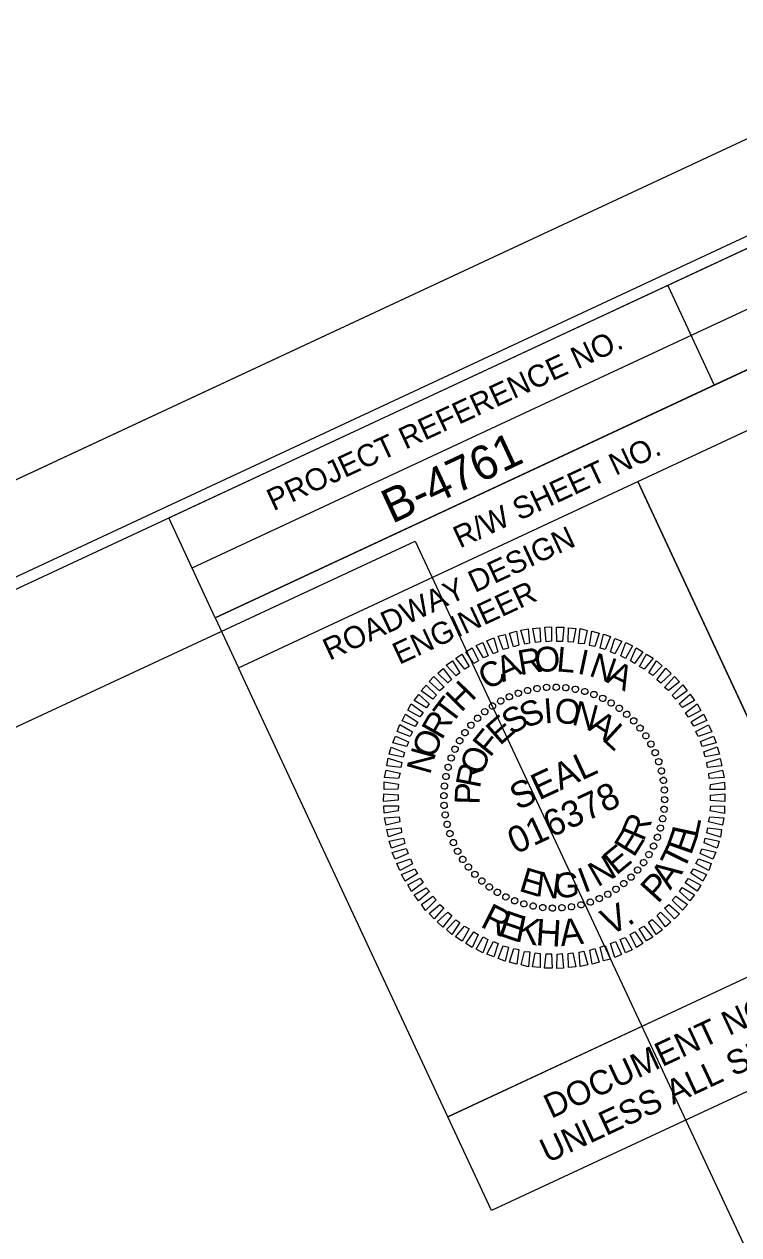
# Model space of a CAD drawing. Extents: x 2321825 to 2323872, y 921700 to 923436.
# Drawn here: x 2323189.3 to 2323351.6, y 923128.5 to 923403.3 of the extents above; entities that cross this region are included whole.
import ezdxf

# ---------------------------------------------------------------- set-up
doc = ezdxf.new("R2010")
doc.units = 0
for name, color, linetype in [('Sheet Cutting Line CELL', 7, 'Continuous'), ('Sheet Data Field CELL', 7, 'Continuous'), ('Sheet Layout Plan Border', 7, 'Continuous'), ('Sheet Plan And Profile CELL', 7, 'Continuous'), ('Sheet Plot Border Inside CELL', 7, 'Continuous'), ('Sheet Plot Border Outside CELL', 7, 'Continuous'), ('Sheet Professional Seal CELL', 7, 'Continuous'), ('Sheet Sticker Exception Certification CELL', 7, 'Continuous')]:
    doc.layers.add(name, color=color, linetype=linetype)

# ---------------------------------------------------------------- blocks, each defined once
blk = doc.blocks.new('STICKER EXCEPTION CERTIFICATION')
at = {"layer": 'Sheet Sticker Exception Certification CELL'}
for p, q in [((0, -0.47), (0, 0)), ((0, 0), (4.0008, 0)), ((4.0008, -0.0003), (4.0008, -0.4703)), ((4.0008, -0.47), (0, -0.47))]:
    blk.add_line(p, q, dxfattribs=at)
for s, p in [('DOCUMENT NOT CONSIDERED FINAL', (0.4214, -0.2069)), ('UNLESS ALL SIGNATURES COMPLETED', (0.32, -0.3829))]:
    blk.add_text(s, height=0.11, dxfattribs=at).set_placement(p)

msp = doc.modelspace()

# ---------------------------------------------------------------- linework, layer by layer
at = {"layer": 'Sheet Cutting Line CELL'}
msp.add_line((2323409.34, 923403.35), (2321883.46, 922692.1), dxfattribs=at)
at = {"layer": 'Sheet Layout Plan Border'}
msp.add_lwpolyline([(2323496.81, 922817.99), (2322321.56, 922264.67), (2322282.6, 922345.71), (2322138.58, 922653.86), (2322100.41, 922737.9), (2323278.09, 923285.95)], close=True, dxfattribs=at)
at = {"layer": 'Sheet Plan And Profile CELL'}
for p, q in [((2323227.42, 923279.88), (2323408.74, 923364.4)), ((2323232.7, 923268.55), (2323414.02, 923353.07)), ((2323335.48, 923344.04), (2323346.04, 923321.38)), ((2323328.66, 923299.49), (2323376.17, 923197.57)), ((2323232.7, 923268.55), (2323237.98, 923257.22))]:
    msp.add_line(p, q, dxfattribs=at)
for points in [[(2323403.44, 923375.77), (2322043.88, 922742.05), (2322487.48, 921790.36), (2323847.04, 922424.08)], [(2323222.12, 923291.26), (2323403.44, 923375.77), (2323414.02, 923353.07), (2323232.7, 923268.55)], [(2323328.66, 923299.49), (2323419.3, 923341.74), (2323466.83, 923239.77), (2323376.19, 923197.52)], [(2323237.98, 923257.22), (2323328.66, 923299.49), (2323376.19, 923197.52), (2323285.51, 923155.25)]]:
    msp.add_lwpolyline(points, close=True, dxfattribs=at)
at = {"layer": 'Sheet Plot Border Inside CELL'}
msp.add_lwpolyline([(2322349.41, 921723.24), (2323859.43, 922427.1), (2323413.71, 923383.32), (2321903.69, 922679.47)], close=True, dxfattribs=at)
at = {"layer": 'Sheet Plot Border Outside CELL'}
msp.add_lwpolyline([(2322346.08, 921699.62), (2323871.95, 922410.87), (2323409.34, 923403.35), (2321883.46, 922692.1)], close=True, dxfattribs=at)
at = {"layer": 'Sheet Professional Seal CELL'}
for p, q in [((2323307.94, 923252.79), (2323307.94, 923252.79)), ((2323310.14, 923252.82), (2323310.14, 923252.82)), ((2323299.5, 923250.68), (2323299.5, 923250.68)), ((2323301.56, 923251.47), (2323301.56, 923251.47)), ((2323303.65, 923252.06), (2323303.65, 923252.06)), ((2323305.75, 923252.54), (2323305.75, 923252.54)), ((2323312.33, 923252.74), (2323312.33, 923252.74)), ((2323314.49, 923252.37), (2323314.49, 923252.37)), ((2323316.64, 923251.88), (2323316.64, 923251.88)), ((2323318.68, 923251.18), (2323318.68, 923251.18)), ((2323320.74, 923250.32), (2323320.74, 923250.32)), ((2323295.7, 923248.52), (2323295.7, 923248.52)), ((2323297.53, 923249.7), (2323297.53, 923249.7)), ((2323322.61, 923249.26), (2323322.61, 923249.26)), ((2323324.46, 923248.02), (2323324.46, 923248.02)), ((2323292.23, 923245.8), (2323292.23, 923245.8)), ((2323293.88, 923247.23), (2323293.88, 923247.23)), ((2323326.19, 923246.68), (2323326.19, 923246.68)), ((2323327.76, 923245.2), (2323327.76, 923245.2)), ((2323289.41, 923242.5), (2323289.41, 923242.5)), ((2323290.75, 923244.23), (2323290.75, 923244.23)), ((2323329.19, 923243.55), (2323329.19, 923243.55)), ((2323288.17, 923240.65), (2323288.17, 923240.65)), ((2323330.48, 923241.73), (2323330.48, 923241.73)), ((2323331.66, 923239.91), (2323331.66, 923239.91)), ((2323286.25, 923236.72), (2323286.25, 923236.72)), ((2323287.11, 923238.78), (2323287.11, 923238.78)), ((2323332.63, 923237.93), (2323332.63, 923237.93)), ((2323285.55, 923234.69), (2323285.55, 923234.69)), ((2323333.43, 923235.88), (2323333.43, 923235.88)), ((2323334.02, 923233.78), (2323334.02, 923233.78)), ((2323285.06, 923232.53), (2323285.06, 923232.53)), ((2323334.5, 923231.69), (2323334.5, 923231.69)), ((2323284.61, 923228.18), (2323284.61, 923228.18)), ((2323284.69, 923230.37), (2323284.69, 923230.37)), ((2323334.75, 923229.49), (2323334.75, 923229.49)), ((2323284.64, 923225.99), (2323284.64, 923225.99)), ((2323309.69, 923227.74), (2323309.69, 923227.74)), ((2323334.78, 923227.29), (2323334.78, 923227.29)), ((2323284.89, 923223.79), (2323284.89, 923223.79)), ((2323334.33, 923222.94), (2323334.33, 923222.94)), ((2323334.7, 923225.1), (2323334.7, 923225.1)), ((2323285.37, 923221.69), (2323285.37, 923221.69)), ((2323333.84, 923220.79), (2323333.84, 923220.79)), ((2323285.96, 923219.6), (2323285.96, 923219.6)), ((2323286.75, 923217.54), (2323286.75, 923217.54)), ((2323333.14, 923218.75), (2323333.14, 923218.75)), ((2323287.73, 923215.57), (2323287.73, 923215.57)), ((2323331.22, 923214.82), (2323331.22, 923214.82)), ((2323332.27, 923216.69), (2323332.27, 923216.69)), ((2323288.91, 923213.74), (2323288.91, 923213.74)), ((2323290.2, 923211.92), (2323290.2, 923211.92)), ((2323329.98, 923212.97), (2323329.98, 923212.97)), ((2323291.63, 923210.27), (2323291.63, 923210.27)), ((2323327.16, 923209.67), (2323327.16, 923209.67)), ((2323328.64, 923211.24), (2323328.64, 923211.24)), ((2323293.2, 923208.8), (2323293.2, 923208.8)), ((2323294.93, 923207.45), (2323294.93, 923207.45)), ((2323296.78, 923206.21), (2323296.78, 923206.21)), ((2323323.69, 923206.95), (2323323.69, 923206.95)), ((2323325.51, 923208.24), (2323325.51, 923208.24)), ((2323298.65, 923205.16), (2323298.65, 923205.16)), ((2323300.71, 923204.29), (2323300.71, 923204.29)), ((2323302.75, 923203.59), (2323302.75, 923203.59)), ((2323315.74, 923203.41), (2323315.74, 923203.41)), ((2323317.83, 923204), (2323317.83, 923204)), ((2323319.89, 923204.8), (2323319.89, 923204.8)), ((2323321.86, 923205.77), (2323321.86, 923205.77)), ((2323304.9, 923203.11), (2323304.9, 923203.11)), ((2323307.06, 923202.73), (2323307.06, 923202.73)), ((2323309.25, 923202.65), (2323309.25, 923202.65)), ((2323311.44, 923202.68), (2323311.44, 923202.68)), ((2323313.64, 923202.93), (2323313.64, 923202.93))]:
    msp.add_line(p, q, dxfattribs=at)
for points in [[(2323295.78, 923260.42), (2323294.41, 923263.37), (2323295.93, 923264.02), (2323296.89, 923260.88)], [(2323298.11, 923261.34), (2323296.92, 923264.37), (2323298.54, 923264.79), (2323299.29, 923261.67)], [(2323300.46, 923261.99), (2323299.51, 923265.08), (2323301.11, 923265.55), (2323301.61, 923262.36)], [(2323303, 923262.57), (2323302.08, 923265.73), (2323303.79, 923266.08), (2323304.06, 923262.79)], [(2323305.45, 923262.99), (2323304.82, 923266.12), (2323306.44, 923266.32), (2323306.55, 923263.12)], [(2323307.87, 923263.13), (2323307.58, 923266.47), (2323309.1, 923266.52), (2323309.06, 923263.3)], [(2323310.31, 923263.22), (2323310.2, 923266.42), (2323311.9, 923266.44), (2323311.54, 923263.19)], [(2323312.88, 923263.15), (2323312.9, 923266.3), (2323314.62, 923266.17), (2323314, 923263.01)], [(2323315.22, 923262.75), (2323315.58, 923266.12), (2323317.2, 923265.71), (2323316.47, 923262.67)], [(2323317.71, 923262.26), (2323318.23, 923265.53), (2323319.87, 923265.08), (2323318.87, 923262.02)], [(2323320.09, 923261.65), (2323320.85, 923264.88), (2323322.44, 923264.29), (2323321.27, 923261.37)], [(2323322.46, 923260.83), (2323323.42, 923263.87), (2323325.01, 923263.28), (2323323.48, 923260.42)], [(2323291.43, 923258.17), (2323289.58, 923260.84), (2323291.03, 923261.74), (2323292.45, 923258.81)], [(2323293.59, 923259.45), (2323291.99, 923262.29), (2323293.5, 923262.94), (2323294.7, 923259.91)], [(2323324.81, 923259.94), (2323325.94, 923262.95), (2323327.46, 923262.17), (2323325.86, 923259.32)], [(2323326.99, 923258.8), (2323328.32, 923261.74), (2323329.8, 923260.83), (2323327.93, 923258.19)], [(2323287.44, 923255.37), (2323285.15, 923257.78), (2323286.55, 923258.82), (2323288.28, 923256.04)], [(2323289.38, 923256.88), (2323287.3, 923259.44), (2323288.73, 923260.28), (2323290.4, 923257.52)], [(2323329.03, 923257.49), (2323330.63, 923260.33), (2323332.13, 923259.38), (2323330.09, 923256.88)], [(2323331.14, 923256.05), (2323332.94, 923258.82), (2323334.18, 923257.69), (2323332.09, 923255.44)], [(2323285.54, 923253.77), (2323283.23, 923256), (2323284.44, 923257.06), (2323286.34, 923254.53)], [(2323332.96, 923254.52), (2323335, 923257.13), (2323336.26, 923255.95), (2323333.87, 923253.74)], [(2323282.1, 923250.13), (2323279.47, 923251.99), (2323280.58, 923253.28), (2323282.91, 923251)], [(2323283.65, 923252.01), (2323281.25, 923254.09), (2323282.36, 923255.26), (2323284.66, 923252.81)], [(2323334.76, 923252.77), (2323336.98, 923255.24), (2323338.13, 923254.07), (2323335.66, 923252.03)], [(2323336.5, 923250.93), (2323338.92, 923253.33), (2323339.89, 923251.96), (2323337.26, 923250.13)], [(2323280.66, 923248.13), (2323277.84, 923249.79), (2323278.91, 923251.17), (2323281.27, 923249.07)], [(2323338.06, 923249.01), (2323340.52, 923251.2), (2323341.51, 923249.79), (2323338.78, 923248.19)], [(2323279.19, 923246.07), (2323276.44, 923247.6), (2323277.22, 923249.01), (2323279.94, 923247.08)], [(2323339.48, 923247.03), (2323342.13, 923249.04), (2323342.99, 923247.56), (2323340.17, 923246.02)], [(2323278.11, 923243.9), (2323275.14, 923245.17), (2323275.92, 923246.69), (2323278.69, 923244.89)], [(2323340.77, 923244.98), (2323343.55, 923246.71), (2323344.35, 923245.22), (2323341.37, 923243.93)], [(2323276.95, 923241.65), (2323274.02, 923242.72), (2323274.61, 923244.31), (2323277.51, 923242.69)], [(2323341.87, 923242.73), (2323344.75, 923244.24), (2323345.47, 923242.7), (2323342.38, 923241.65)], [(2323275.41, 923236.91), (2323272.23, 923237.58), (2323272.68, 923239.22), (2323275.66, 923238.02)], [(2323276.19, 923239.37), (2323273.01, 923240.15), (2323273.66, 923241.72), (2323276.58, 923240.43)], [(2323342.88, 923240.45), (2323345.87, 923241.73), (2323346.48, 923240.19), (2323343.3, 923239.32)], [(2323343.67, 923238.17), (2323346.7, 923239.25), (2323347.23, 923237.62), (2323343.95, 923236.97)], [(2323274.85, 923234.55), (2323271.69, 923234.95), (2323271.93, 923236.67), (2323275.04, 923235.69)], [(2323344.38, 923235.69), (2323347.36, 923236.63), (2323347.76, 923234.94), (2323344.46, 923234.57)], [(2323274.34, 923232.11), (2323271.17, 923232.28), (2323271.48, 923233.98), (2323274.68, 923233.26)], [(2323344.81, 923233.24), (2323347.89, 923233.96), (2323348.27, 923232.31), (2323344.89, 923232.12)], [(2323274.16, 923229.65), (2323271.05, 923229.58), (2323271.07, 923231.3), (2323274.3, 923230.77)], [(2323345.14, 923230.74), (2323348.33, 923231.24), (2323348.4, 923229.56), (2323345.09, 923229.56)], [(2323274.22, 923227.14), (2323270.93, 923226.88), (2323270.95, 923228.6), (2323274.21, 923228.35)], [(2323345.17, 923228.33), (2323348.46, 923228.59), (2323348.44, 923226.87), (2323345.18, 923227.12)], [(2323274.25, 923224.73), (2323271.06, 923224.23), (2323270.99, 923225.91), (2323274.3, 923225.91)], [(2323345.23, 923225.82), (2323348.34, 923225.89), (2323348.32, 923224.17), (2323345.09, 923224.71)], [(2323274.58, 923222.24), (2323271.5, 923221.52), (2323271.12, 923223.16), (2323274.5, 923223.36)], [(2323345.05, 923223.36), (2323348.22, 923223.19), (2323347.91, 923221.5), (2323344.71, 923222.21)], [(2323275.01, 923219.79), (2323272.03, 923218.84), (2323271.63, 923220.53), (2323274.92, 923220.91)], [(2323344.54, 923220.92), (2323347.7, 923220.52), (2323347.45, 923218.8), (2323344.35, 923219.78)], [(2323275.72, 923217.31), (2323272.69, 923216.23), (2323272.16, 923217.85), (2323275.44, 923218.5)], [(2323343.98, 923218.56), (2323347.16, 923217.89), (2323346.71, 923216.25), (2323343.73, 923217.45)], [(2323276.51, 923215.03), (2323273.52, 923213.74), (2323272.91, 923215.28), (2323276.09, 923216.16)], [(2323343.2, 923216.1), (2323346.37, 923215.32), (2323345.73, 923213.75), (2323342.81, 923215.04)], [(2323277.52, 923212.74), (2323274.64, 923211.23), (2323273.92, 923212.77), (2323277.01, 923213.83)], [(2323341.28, 923211.57), (2323344.25, 923210.3), (2323343.47, 923208.78), (2323340.7, 923210.58)], [(2323342.44, 923213.82), (2323345.36, 923212.75), (2323344.78, 923211.16), (2323341.88, 923212.78)], [(2323278.62, 923210.49), (2323275.84, 923208.76), (2323275.03, 923210.26), (2323278.02, 923211.54)], [(2323279.91, 923208.44), (2323277.26, 923206.44), (2323276.4, 923207.91), (2323279.22, 923209.45)], [(2323340.19, 923209.41), (2323342.95, 923207.88), (2323342.17, 923206.47), (2323339.45, 923208.4)], [(2323281.33, 923206.46), (2323278.87, 923204.27), (2323277.88, 923205.68), (2323280.61, 923207.28)], [(2323338.73, 923207.34), (2323341.55, 923205.68), (2323340.48, 923204.3), (2323338.12, 923206.4)], [(2323282.89, 923204.54), (2323280.47, 923202.14), (2323279.5, 923203.51), (2323282.12, 923205.34)], [(2323284.62, 923202.7), (2323282.41, 923200.23), (2323281.26, 923201.41), (2323283.73, 923203.44)], [(2323335.74, 923203.47), (2323338.14, 923201.39), (2323337.03, 923200.21), (2323334.73, 923202.67)], [(2323337.29, 923205.35), (2323339.92, 923203.49), (2323338.81, 923202.2), (2323336.48, 923204.47)], [(2323286.43, 923200.95), (2323284.39, 923198.34), (2323283.13, 923199.52), (2323285.51, 923201.74)], [(2323333.85, 923201.71), (2323336.16, 923199.47), (2323334.95, 923198.41), (2323333.05, 923200.94)], [(2323288.25, 923199.42), (2323286.45, 923196.66), (2323285.21, 923197.79), (2323287.3, 923200.03)], [(2323290.36, 923197.98), (2323288.76, 923195.14), (2323287.26, 923196.1), (2323289.3, 923198.59)], [(2323330.01, 923198.59), (2323332.09, 923196.03), (2323330.66, 923195.19), (2323328.99, 923197.95)], [(2323331.95, 923200.1), (2323334.24, 923197.69), (2323332.84, 923196.66), (2323331.11, 923199.43)], [(2323292.4, 923196.67), (2323291.07, 923193.73), (2323289.59, 923194.65), (2323291.45, 923197.28)], [(2323294.58, 923195.54), (2323293.45, 923192.53), (2323291.93, 923193.31), (2323293.53, 923196.15)], [(2323325.8, 923196.02), (2323327.4, 923193.18), (2323325.88, 923192.53), (2323324.69, 923195.56)], [(2323327.96, 923197.3), (2323329.81, 923194.64), (2323328.36, 923193.74), (2323326.94, 923196.66)], [(2323296.93, 923194.64), (2323295.97, 923191.61), (2323294.38, 923192.19), (2323295.91, 923195.05)], [(2323299.3, 923193.82), (2323298.54, 923190.6), (2323296.95, 923191.18), (2323298.12, 923194.1)], [(2323301.68, 923193.22), (2323301.16, 923189.94), (2323299.52, 923190.39), (2323300.52, 923193.45)], [(2323304.17, 923192.72), (2323303.81, 923189.36), (2323302.19, 923189.76), (2323302.92, 923192.8)], [(2323306.51, 923192.32), (2323306.49, 923189.17), (2323304.77, 923189.31), (2323305.39, 923192.47)], [(2323311.52, 923192.34), (2323311.81, 923189), (2323310.28, 923188.95), (2323310.33, 923192.17)], [(2323313.94, 923192.48), (2323314.57, 923189.35), (2323312.95, 923189.15), (2323312.84, 923192.35)], [(2323316.39, 923192.9), (2323317.31, 923189.75), (2323315.6, 923189.39), (2323315.33, 923192.69)], [(2323318.93, 923193.48), (2323319.88, 923190.39), (2323318.27, 923189.92), (2323317.78, 923193.11)], [(2323321.28, 923194.13), (2323322.47, 923191.1), (2323320.85, 923190.68), (2323320.1, 923193.81)], [(2323323.6, 923195.05), (2323324.98, 923192.11), (2323323.46, 923191.46), (2323322.5, 923194.59)], [(2323309.08, 923192.25), (2323309.19, 923189.05), (2323307.49, 923189.03), (2323307.85, 923192.29)]]:
    msp.add_lwpolyline(points, close=True, dxfattribs=at)
for centre, major_axis in [((2323303.63, 923252.07), (-0.174, 0.699)), ((2323305.77, 923252.51), (-0.113, 0.711)), ((2323307.95, 923252.76), (-0.05, 0.718)), ((2323310.14, 923252.81), (0.013, 0.72)), ((2323312.32, 923252.68), (0.075, 0.716)), ((2323314.48, 923252.35), (0.137, 0.707)), ((2323297.54, 923249.67), (-0.349, 0.63)), ((2323299.5, 923250.65), (-0.293, 0.658)), ((2323301.53, 923251.45), (-0.234, 0.681)), ((2323316.61, 923251.84), (0.199, 0.692)), ((2323318.69, 923251.15), (0.258, 0.672)), ((2323320.69, 923250.28), (0.316, 0.647)), ((2323322.61, 923249.23), (0.371, 0.617)), ((2323293.91, 923247.23), (-0.453, 0.56)), ((2323295.67, 923248.53), (-0.403, 0.597)), ((2323324.44, 923248.02), (0.423, 0.582)), ((2323326.15, 923246.66), (0.472, 0.543)), ((2323290.77, 923244.19), (-0.543, 0.472)), ((2323292.28, 923245.78), (-0.5, 0.518)), ((2323327.74, 923245.16), (0.518, 0.5)), ((2323289.41, 923242.48), (-0.582, 0.423)), ((2323329.19, 923243.52), (0.56, 0.453)), ((2323330.49, 923241.76), (0.597, 0.403)), ((2323287.15, 923238.73), (-0.647, 0.316)), ((2323288.2, 923240.66), (-0.617, 0.371)), ((2323331.63, 923239.89), (0.63, 0.349)), ((2323286.28, 923236.73), (-0.672, 0.258)), ((2323332.61, 923237.93), (0.658, 0.293)), ((2323333.41, 923235.9), (0.681, 0.234)), ((2323285.59, 923234.65), (-0.692, 0.199)), ((2323334.03, 923233.8), (0.699, 0.174)), ((2323284.75, 923230.36), (-0.716, 0.075)), ((2323285.08, 923232.53), (-0.707, 0.137)), ((2323334.47, 923231.66), (0.711, 0.113)), ((2323284.62, 923228.18), (-0.72, 0.013)), ((2323334.71, 923229.48), (0.718, 0.05)), ((2323284.68, 923225.99), (-0.718, -0.05)), ((2323334.64, 923225.11), (0.716, -0.075)), ((2323334.77, 923227.29), (0.72, -0.013)), ((2323284.92, 923223.82), (-0.711, -0.113)), ((2323334.31, 923222.95), (0.707, -0.137)), ((2323285.36, 923221.67), (-0.699, -0.174)), ((2323285.98, 923219.57), (-0.681, -0.234)), ((2323333.8, 923220.82), (0.692, -0.199)), ((2323286.78, 923217.54), (-0.658, -0.293)), ((2323332.23, 923216.74), (0.647, -0.316)), ((2323333.11, 923218.74), (0.672, -0.258)), ((2323287.76, 923215.58), (-0.63, -0.349)), ((2323288.9, 923213.71), (-0.597, -0.403)), ((2323331.19, 923214.82), (0.617, -0.371)), ((2323290.2, 923211.96), (-0.56, -0.453)), ((2323328.62, 923211.28), (0.543, -0.472)), ((2323329.98, 923212.99), (0.582, -0.423)), ((2323291.65, 923210.32), (-0.518, -0.5)), ((2323293.24, 923208.81), (-0.472, -0.543)), ((2323325.47, 923208.24), (0.453, -0.56)), ((2323327.11, 923209.69), (0.5, -0.518)), ((2323294.95, 923207.45), (-0.423, -0.582)), ((2323296.77, 923206.24), (-0.371, -0.617)), ((2323321.85, 923205.8), (0.349, -0.63)), ((2323323.72, 923206.94), (0.403, -0.597)), ((2323298.7, 923205.2), (-0.316, -0.647)), ((2323300.7, 923204.32), (-0.258, -0.672)), ((2323302.78, 923203.63), (-0.199, -0.692)), ((2323304.91, 923203.12), (-0.137, -0.707)), ((2323307.07, 923202.79), (-0.075, -0.716)), ((2323309.25, 923202.66), (-0.013, -0.72)), ((2323311.44, 923202.72), (0.05, -0.718)), ((2323313.61, 923202.96), (0.113, -0.711)), ((2323315.76, 923203.4), (0.174, -0.699)), ((2323317.86, 923204.02), (0.234, -0.681)), ((2323319.89, 923204.82), (0.293, -0.658))]:
    msp.add_ellipse(centre, major_axis=major_axis, ratio=0.999708, dxfattribs=at)

# ---------------------------------------------------------------- block references
at = {"layer": 'Sheet Cutting Line CELL', "xscale": 49.99999999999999, "yscale": 50, "rotation": 24.991298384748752}
msp.add_blockref('STICKER EXCEPTION CERTIFICATION', (2323285.52, 923155.26), dxfattribs=at)

# ---------------------------------------------------------------- texts
at = {"layer": 'Sheet Data Field CELL'}
msp.add_text('B-4761', height=7.75, rotation=24.9913, dxfattribs=at).set_placement((2323272.85, 923289.86))
at = {"layer": 'Sheet Plan And Profile CELL'}
for s, height, p in [('PROJECT REFERENCE NO.', 5.0001, (2323245.91, 923292.75)), ('R/W SHEET NO.', 5.0001, (2323288.25, 923284.29)), ('ROADWAY DESIGN', 5.0001, (2323258.65, 923258.8)), ('ENGINEER', 5, (2323274.48, 923257.85))]:
    msp.add_text(s, height=height, rotation=24.9913, dxfattribs=at).set_placement(p)
at = {"layer": 'Sheet Professional Seal CELL'}
for s, height, rotation, p in [('R', 5.64, 9.6124, (2323301.93, 923255.51)), ('O', 5.64, 2.4125, (2323305.29, 923256.24)), ('L', 5.64, 355.2122, (2323310.06, 923256.43)), ('I', 5.64, 348.0114, (2323314.74, 923255.96)), ('C', 5.64, 31.2112, (2323294.59, 923251.97)), ('A', 5.64, 24.0116, (2323298.04, 923253.91)), ('N', 5.64, 340.8102, (2323317.35, 923255.46)), ('A', 5.64, 333.6085, (2323321.27, 923254.04)), ('H', 5.64, 45.6108, (2323288.55, 923246.95)), ('T', 5.64, 52.8111, (2323286.3, 923244.08)), ('I', 5.64, 4.1809, (2323307.47, 923244.57)), ('O', 5.64, 354.8248, (2323309.58, 923244.78)), ('S', 5.64, 32.2469, (2323300.04, 923241.83)), ('S', 5.64, 22.8917, (2323303.28, 923243.39)), ('N', 5.64, 345.4679, (2323313.46, 923244.39)), ('R', 5.64, 60.0118, (2323284.15, 923240.65)), ('E', 5.64, 41.6024, (2323297.35, 923239.42)), ('A', 5.64, 326.7516, (2323317.14, 923243.23)), ('L', 5.64, 317.3921, (2323320.37, 923240.93)), ('O', 5.64, 67.213, (2323282.33, 923236.38)), ('F', 5.64, 50.9583, (2323295.09, 923236.7)), ('O', 5.64, 69.6725, (2323293.34, 923232.64)), ('N', 5.64, 74.4148, (2323281.47, 923232.78)), ('SEAL', 5.998, 24.9913, (2323301.36, 923224.79)), ('R', 5.64, 79.0309, (2323292.79, 923229.68)), ('P', 5.64, 88.3902, (2323292.69, 923226.1)), ('016378', 5.998, 24.9913, (2323300.9, 923214.8)), ('R', 5.64, 67.4727, (2323329.97, 923217.6)), ('L', 6, 77.7163, (2323342.16, 923218.42)), ('E', 5.64, 58.1154, (2323327.75, 923213.98)), ('E', 6, 70.607, (2323340.75, 923214.47)), ('E', 5.64, 39.4031, (2323323.77, 923209.97)), ('T', 6, 63.8067, (2323338.96, 923210.89)), ('N', 5.64, 30.0477, (2323319.54, 923207.33)), ('E', 5.64, 343.2682, (2323301.44, 923206.62)), ('I', 5.64, 20.6925, (2323316.44, 923206.05)), ('A', 6, 54.9664, (2323336.03, 923206.59)), ('N', 5.64, 352.6253, (2323305.3, 923205.44)), ('G', 5.64, 1.9815, (2323309.7, 923205.01)), ('P', 6, 47.8571, (2323333.21, 923203.49)), ('R', 6, 333.4718, (2323292.67, 923198.57)), ('V', 6, 25.3699, (2323322.15, 923196.34)), ('E', 6, 340.952, (2323296.62, 923196.6)), ('K', 6, 348.0614, (2323300.57, 923195.22)), ('H', 6, 356.3453, (2323305.35, 923194.24)), ('A', 6, 6.3293, (2323311.22, 923194)), ('.', 6, 33.623, (2323326.52, 923198.46))]:
    msp.add_text(s, height=height, rotation=rotation, dxfattribs=at).set_placement(p)

doc.saveas('drawing.dxf')
